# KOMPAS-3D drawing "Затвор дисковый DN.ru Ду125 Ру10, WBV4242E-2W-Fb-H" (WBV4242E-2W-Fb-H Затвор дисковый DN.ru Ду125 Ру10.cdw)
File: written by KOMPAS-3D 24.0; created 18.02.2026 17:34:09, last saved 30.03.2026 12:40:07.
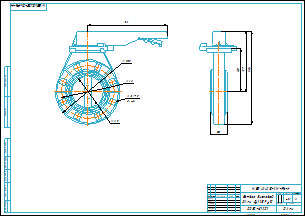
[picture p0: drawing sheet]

Document properties: Автор: R2D2; Форматы листов документа: A2; Полное имя файла: WBV4242E-2W-Fb-H Затвор дисковый DN.ru Ду125 Ру10.m3d; Масса: 4.31; Наименование: Затвор дисковый DN.ru Ду125 Ру10; Количество листов документа: 1; Примечание: D050-81201

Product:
- Part/product: Затвор дисковый DN.ru Ду125 Ру10  | designation WBV4242E-2W-Fb-H
    Масса: 4.31
    Раздел спецификации: Прочие изделия
    Примечание: D050-81201

Views: Проекционный вид 2
Referenced files in E:\Работа\Зайцев\WBV4242E-2W-Fb-ISO Затвор дисковый DN.ru Ду50-200 Ру10\DN125\: WBV4242E-2W-Fb-ISO Затвор дисковый DN.ru Ду125 Ру10.m3d
Referenced files in E:\Работа\Зайцев\Для компаса\: чертеж DN.ru А3.cdt
Referenced files in E:\Работа\Зайцев\WBV4242E-2W-Fb-H Затвор дисковый DN.ru Ду50-200 Ру10\DN125\: WBV4242E-2W-Fb-H Затвор дисковый DN.ru Ду125 Ру10.m3d
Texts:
  WBV4242E-2W-Fb-H
  чертеж DN.ru А3.cdt
  Затвор дисковый
  DN.ru Ду125 Ру10
  Затвор дисковый DN.ru Ду125 Ру10
  WBV4242E-2W-Fb-H Затвор дисковый DN.ru Ду125 Ру10
Dimensions and other numbers on the sheet: 0; 3; 4; 169; 63; 364; 237; 1:2; 1; 2; 4,31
